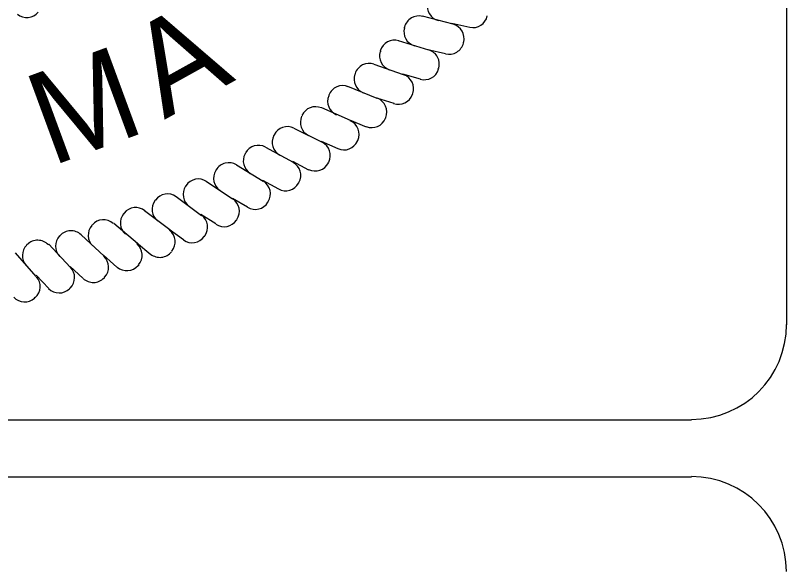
# Model space of a CAD drawing. Extents: x 1458004.1 to 1458040.9, y 194172.7 to 194198.1.
# Drawn here: x 1458038.688 to 1458039.5, y 194175.948 to 194176.533 of the extents above; entities that cross this region are included whole.
import ezdxf

# ---------------------------------------------------------------- set-up
doc = ezdxf.new("R2010")
doc.units = 0
for name, color, linetype in [('Eng_Stamp', 7, 'Continuous'), ('Eng_Stamp_Text_4', 7, 'Continuous'), ('Text_Box_4', 7, 'Continuous')]:
    doc.layers.add(name, color=color, linetype=linetype)

msp = doc.modelspace()

# ---------------------------------------------------------------- linework, layer by layer
at = {"layer": 'Eng_Stamp'}
for p, q in [((1458039.14917, 194176.52417), (1458039.11667, 194176.5325)), ((1458039.0975, 194176.52083), (1458039.0975, 194176.52)), ((1458039.1475, 194176.525), (1458039.16667, 194176.52083)), ((1458039.12333, 194176.49667), (1458039.09167, 194176.50667)), ((1458039.16, 194176.50417), (1458039.16, 194176.505)), ((1458039.0725, 194176.49583), (1458039.0725, 194176.495)), ((1458039.1225, 194176.4975), (1458039.14083, 194176.49333)), ((1458039.09667, 194176.47083), (1458039.06583, 194176.48167)), ((1458039.13333, 194176.47667), (1458039.13333, 194176.4775)), ((1458039.04583, 194176.4725), (1458039.04583, 194176.47167)), ((1458039.09583, 194176.47167), (1458039.11417, 194176.46667)), ((1458039.06917, 194176.44583), (1458039.03833, 194176.45833)), ((1458039.01833, 194176.44917), (1458039.01833, 194176.44833)), ((1458039.06833, 194176.44667), (1458039.08667, 194176.44083)), ((1458039.10583, 194176.45), (1458039.10667, 194176.45083)), ((1458039.04083, 194176.4225), (1458039.01083, 194176.43583)), ((1458038.99, 194176.4275), (1458038.99, 194176.4275)), ((1458039.04, 194176.42333), (1458039.0575, 194176.41583)), ((1458039.07833, 194176.425), (1458039.07833, 194176.42583)), ((1458039.01083, 194176.4), (1458038.98167, 194176.41417)), ((1458038.96083, 194176.4075), (1458038.96, 194176.40667)), ((1458039.01, 194176.40083), (1458039.0275, 194176.39333)), ((1458039.04833, 194176.40083), (1458039.04833, 194176.40167)), ((1458038.93, 194176.38833), (1458038.93, 194176.3875)), ((1458038.98083, 194176.37833), (1458038.95167, 194176.39417)), ((1458038.94917, 194176.35833), (1458038.92083, 194176.37583)), ((1458038.98, 194176.38), (1458038.99667, 194176.37083)), ((1458039.0175, 194176.37833), (1458039.01833, 194176.37917)), ((1458038.89917, 194176.37083), (1458038.89917, 194176.37)), ((1458038.91667, 194176.34), (1458038.88917, 194176.35833)), ((1458038.94833, 194176.36), (1458038.965, 194176.35083)), ((1458038.98667, 194176.35667), (1458038.98667, 194176.3575)), ((1458038.8675, 194176.35417), (1458038.8675, 194176.35333)), ((1458038.88417, 194176.3225), (1458038.8575, 194176.3425)), ((1458038.91667, 194176.34083), (1458038.9325, 194176.33167)), ((1458038.83583, 194176.33917), (1458038.835, 194176.33833)), ((1458038.95417, 194176.33667), (1458038.95417, 194176.3375)), ((1458038.8025, 194176.325), (1458038.8025, 194176.32417)), ((1458038.85083, 194176.3075), (1458038.82417, 194176.3275)), ((1458038.88333, 194176.32417), (1458038.89917, 194176.31417)), ((1458038.92083, 194176.31833), (1458038.92167, 194176.31833)), ((1458038.76917, 194176.31333), (1458038.76917, 194176.3125)), ((1458038.81667, 194176.29333), (1458038.79167, 194176.31417)), ((1458038.85, 194176.30833), (1458038.865, 194176.2975)), ((1458038.735, 194176.30167), (1458038.735, 194176.30083)), ((1458038.78167, 194176.28), (1458038.7575, 194176.3025)), ((1458038.88667, 194176.30083), (1458038.8875, 194176.30083)), ((1458038.70083, 194176.2925), (1458038.7, 194176.29167)), ((1458038.74583, 194176.26833), (1458038.72333, 194176.2925)), ((1458038.81583, 194176.29417), (1458038.83083, 194176.28167)), ((1458038.71, 194176.25833), (1458038.68833, 194176.28333)), ((1458038.8525, 194176.285), (1458038.8525, 194176.285)), ((1458038.78083, 194176.28083), (1458038.795, 194176.26833)), ((1458038.74583, 194176.26917), (1458038.75917, 194176.25667)), ((1458038.8175, 194176.27), (1458038.81833, 194176.27083)), ((1458038.71, 194176.26), (1458038.72333, 194176.24583)), ((1458038.78167, 194176.2575), (1458038.7825, 194176.2575)), ((1458038.745, 194176.24583), (1458038.74583, 194176.24667)), ((1458038.70833, 194176.23583), (1458038.70917, 194176.23667))]:
    msp.add_line(p, q, dxfattribs=at)
for centre, start, end in [((1458039.13736, 194176.54294), 168, 255.38537), ((1458038.7001, 194176.54661), 231.17572, 321.17572), ((1458039.11295, 194176.51715), 75.6, 165.6), ((1458039.16976, 194176.53601), 258, 348), ((1458039.11273, 194176.51632), 165.6, 252.98537), ((1458039.14503, 194176.50888), 345.6, 75.6), ((1458039.08726, 194176.49158), 73.2, 163.2), ((1458039.14482, 194176.50804), 255.6, 345.6), ((1458039.08701, 194176.49075), 163.2, 250.58537), ((1458039.11897, 194176.48197), 343.2, 73.2), ((1458039.06052, 194176.4671), 70.8, 160.8), ((1458039.06024, 194176.46628), 160.8, 248.18538), ((1458039.0918, 194176.45617), 340.8, 70.8), ((1458039.11872, 194176.48114), 253.2, 343.2), ((1458039.03279, 194176.44376), 68.4, 158.4), ((1458039.03247, 194176.44295), 158.4, 245.78537), ((1458039.06358, 194176.43153), 338.4, 68.4), ((1458039.09152, 194176.45535), 250.8, 340.8), ((1458039.0041, 194176.4216), 66, 156), ((1458039.00374, 194176.42081), 156, 243.38538), ((1458039.03435, 194176.40809), 336, 66), ((1458039.06326, 194176.43072), 248.4, 338.4), ((1458038.9745, 194176.40067), 63.6, 153.6), ((1458038.97412, 194176.39989), 153.6, 240.98538), ((1458038.94406, 194176.38099), 61.2, 151.2), ((1458039.00417, 194176.3859), 333.6, 63.6), ((1458039.034, 194176.4073), 246, 336), ((1458038.94364, 194176.38023), 151.2, 238.58537), ((1458038.91282, 194176.3626), 58.8, 148.8), ((1458038.97308, 194176.36499), 331.2, 61.2), ((1458039.00378, 194176.38513), 243.6, 333.6), ((1458038.91237, 194176.36186), 148.8, 236.18538), ((1458038.88083, 194176.34554), 56.4, 146.4), ((1458038.94114, 194176.34541), 328.8, 58.8), ((1458038.97266, 194176.36424), 241.2, 331.2), ((1458038.88035, 194176.34482), 146.4, 233.78538), ((1458038.84816, 194176.32983), 54, 144), ((1458038.90841, 194176.32717), 326.4, 56.4), ((1458038.84766, 194176.32913), 144, 231.38538), ((1458038.94069, 194176.34467), 238.8, 328.8), ((1458038.81433, 194176.31483), 141.6, 228.98538), ((1458038.81486, 194176.31551), 51.6, 141.6), ((1458038.781, 194176.30259), 49.2, 139.2), ((1458038.87495, 194176.31033), 324, 54), ((1458038.90793, 194176.32645), 236.4, 326.4), ((1458038.78043, 194176.30193), 139.2, 226.58538), ((1458038.84081, 194176.2949), 321.6, 51.6), ((1458038.74602, 194176.29047), 136.8, 224.18538), ((1458038.74661, 194176.2911), 46.8, 136.8), ((1458038.87444, 194176.30963), 234, 324), ((1458038.71116, 194176.28046), 134.4, 221.78537), ((1458038.71178, 194176.28106), 44.4, 134.4), ((1458038.80605, 194176.28091), 319.2, 49.2), ((1458038.84027, 194176.29422), 231.6, 321.6), ((1458038.77074, 194176.26839), 316.8, 46.8), ((1458038.73494, 194176.25736), 314.4, 44.4), ((1458038.80549, 194176.28026), 229.2, 319.2), ((1458038.69871, 194176.24784), 312, 42), ((1458038.77015, 194176.26776), 226.8, 316.8), ((1458038.73432, 194176.25676), 224.4, 314.4), ((1458038.69806, 194176.24726), 222, 312)]:
    msp.add_arc(centre, 0.01558, start, end, dxfattribs=at)
at = {"layer": 'Text_Box_4'}
for p, q in [((1458039.5, 194177.94667), (1458039.5, 194176.2075)), ((1458032.09667, 194176.1075), (1458039.4, 194176.1075)), ((1458035.87833, 194176.0475), (1458039.4, 194176.0475))]:
    msp.add_line(p, q, dxfattribs=at)
for centre, start, end in [((1458039.40002, 194176.20814), 270, 0), ((1458039.39985, 194175.94797), 0, 90)]:
    msp.add_arc(centre, 0.1, start, end, dxfattribs=at)

# ---------------------------------------------------------------- texts
at = {"layer": 'Eng_Stamp_Text_4'}
for s, rotation, p in [('A', 29.06022, (1458038.845, 194176.42333)), ('M', 20.20953, (1458038.72583, 194176.37417))]:
    msp.add_text(s, height=0.09749, rotation=rotation, dxfattribs=at).set_placement(p)

doc.saveas('drawing.dxf')
